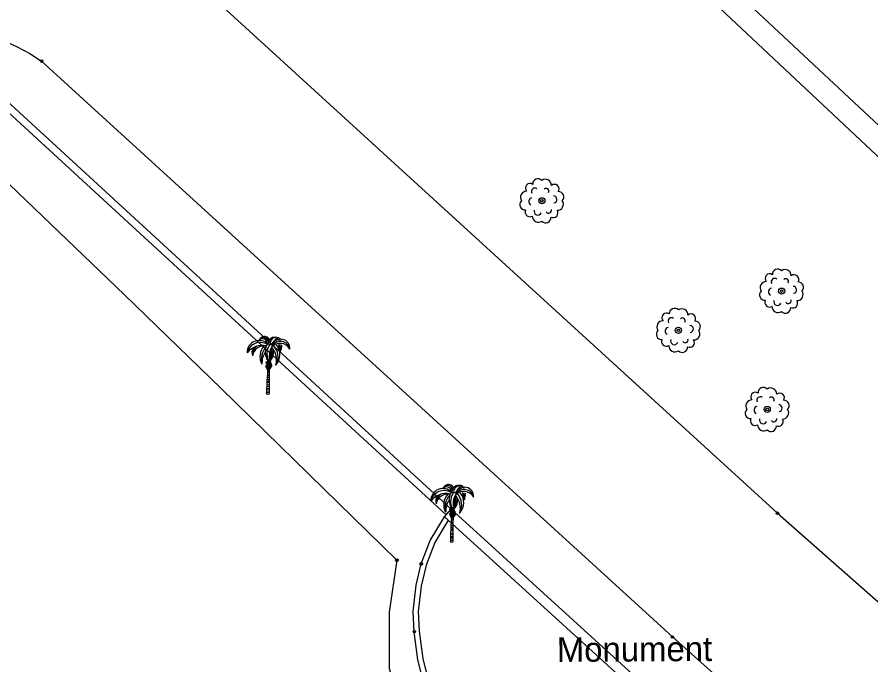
# Model space of a CAD drawing. Extents: x 344013 to 344423, y 298505 to 298795.
# Drawn here: x 344098.36 to 344132.25, y 298691.08 to 298716.8 of the extents above; entities that cross this region are included whole.
import ezdxf

# ---------------------------------------------------------------- set-up
doc = ezdxf.new("R2010")
doc.units = 0
for name, color, linetype in [('Default', 7, 'Continuous'), ('DH_CADRE -CARTOUCHE', 7, 'Continuous'), ('GO MUR EXTERIEUR', 7, 'Continuous'), ('PS_BOLT', 7, 'Continuous'), ('PS_CONST', 7, 'Continuous'), ('TOPO_POINT', 7, 'Continuous'), ('VOIRIE_BORDURE', 7, 'Continuous'), ('VOIRIE_ESPACE VERT', 7, 'Continuous')]:
    doc.layers.add(name, color=color, linetype=linetype)

# ---------------------------------------------------------------- blocks, each defined once
blk = doc.blocks.new('POINT_DISPLAY')
at = {"layer": 'Default'}
blk.add_circle((0, 0), 0.05, dxfattribs=at)
blk = doc.blocks.new('ARB1')
at = {"layer": 'Default'}
blk.add_circle((0, 0), 0.122, dxfattribs=at)
for centre, radius, start, end in [((-0.471, 0.503), 0.183, 53.9554, 222.2066), ((-0.153, 0.664), 0.211, 43.6925, 183.5969), ((0.139, 0.613), 0.241, 358.4583, 125.1928), ((-0.613, 0.139), 0.241, 88.4583, 215.1928), ((-0.276, 0.37), 0.134, 52.4396, 209.5496), ((0.164, 0.38), 0.112, 330.5895, 133.7127), ((0.501, 0.468), 0.183, 325.1444, 131.0175), ((0.664, 0.153), 0.211, 313.6925, 93.5969), ((-0.373, -0.024), 0.149, 103.7092, 242.3465), ((0.458, 0.052), 0.137, 276.6214, 88.967), ((0.613, -0.139), 0.241, 268.4583, 35.1928), ((-0.664, -0.153), 0.211, 133.6925, 273.5969), ((-0.478, -0.443), 0.19, 155.2243, 300.9377), ((-0.139, -0.613), 0.241, 178.4583, 305.1928), ((-0.163, -0.42), 0.148, 159.5371, 338.1663), ((0.153, -0.664), 0.211, 223.6925, 3.5969), ((0.271, -0.38), 0.112, 210.5895, 13.7127), ((0.448, -0.483), 0.188, 243.1323, 33.0297)]:
    blk.add_arc(centre, radius, start, end, dxfattribs=at)
blk = doc.blocks.new('PALMIER')
at = {"layer": 'Default'}
for p, q in [((0.066, 0.879), (-0.031, 0.865)), ((-0.027, 0.942), (0.068, 0.953)), ((0.07, 1.023), (-0.02, 1.046)), ((-0.016, 1.111), (0.072, 1.097)), ((-0.051, 0.409), (0.059, 0.425)), ((0.06, 0.53), (-0.047, 0.516)), ((-0.036, 0.77), (0.064, 0.807)), ((-0.062, 0.035), (0.058, 0.076)), ((0.058, 0.159), (-0.059, 0.156)), ((-0.057, 0.24), (0.058, 0.243)), ((0.058, 0.341), (-0.054, 0.323))]:
    blk.add_line(p, q, dxfattribs=at)
blk.add_lwpolyline([(-0.044, 0.591), (0.061, 0.593), (0.062, 0.664), (-0.041, 0.672)], dxfattribs=at)
for centre, radius, start, end in [((-0.427, 2.014), 0.606, 43.7538, 181.6042), ((-0.119, 2.5), 0.329, 122.4892, 158.9053), ((-0.196, 2.528), 0.242, 4.6636, 154.2427), ((-0.249, 2.465), 0.236, 4.3858, 134.352), ((-0.156, 2.558), 0.26, 21.2278, 122.4892), ((0.39, 2.418), 0.379, 113.9098, 175.4727), ((0.39, 2.418), 0.379, 113.9098, 175.4727), ((0.433, 2.437), 0.332, 97.2666, 184.0929), ((1.052, 1.956), 0.976, 126.8275, 153.3081), ((0.636, 2.223), 0.459, 356.3044, 159.1426), ((0.629, 2.092), 0.477, 12.2494, 148.4563), ((0.357, 2.315), 0.459, 69.2234, 105.0038), ((-1.014, 1.466), 1.819, 37.7085, 40.6574), ((-0.251, 2.185), 0.885, 28.6142, 37.2383), ((0.508, 2.682), 0.0691, 35.4622, 126.8275), ((-0.048, 2.285), 0.752, 25.9612, 35.4622), ((-0.287, 1.433), 0.935, 76.8807, 142.9442), ((-0.379, 1.861), 0.66, 58.0609, 166.7618), ((-0.298, 2.021), 0.491, 151.2749, 199.7359), ((-0.191, 1.77), 0.575, 78.6557, 171.4922), ((-0.318, 1.955), 0.441, 119.2251, 188.9038), ((0.377, 1.821), 0.768, 136.853, 208.9638), ((0.57, 1.687), 0.895, 137.8747, 194.5133), ((0.64, 2.063), 0.767, 153.2285, 230.2541), ((0.679, 1.97), 0.731, 142.4971, 222.4211), ((0, 2.373), 0.0573, 81.8892, 144.4453), ((-0.182, 1.095), 1.349, 71.5132, 81.8892), ((0.306, 2.506), 0.261, 198.8183, 199.9044), ((0.989, 1.84), 0.917, 144.1283, 203.5706), ((27.823, 0.039), 27.774, 175.6208, 176.7014), ((0.325, 2.055), 0.223, 141.9977, 191.6592), ((0.414, 2.001), 0.306, 136.5986, 162.2103), ((0.372, 1.986), 0.249, 133.2601, 172.8951), ((-0.403, 1.944), 0.63, 329.6083, 26.821), ((-0.287, 2.01), 0.575, 317.9696, 12.4803), ((0.609, 1.916), 0.559, 29.7072, 139.4934), ((-0.544, 1.637), 0.978, 345.0198, 41.2878), ((-0.338, 1.796), 0.844, 47.1184, 50.2648), ((-0.152, 1.926), 0.754, 51.3892, 54.6634), ((-0.338, 1.796), 0.844, 334.2104, 41.3357), ((-0.152, 1.926), 0.754, 315.2889, 39.1656), ((-1.727, 1.741), 2.37, 7.7396, 16.5083), ((-0.251, 2.185), 0.885, 351.03, 14.848), ((-0.484, 2.461), 1.182, 339.5014, 356.7342), ((0.671, 1.493), 0.966, 145.6563, 182.5945), ((-0.275, 1.529), 0.286, 2.2916, 36.7742), ((0.563, 1.714), 0.483, 137.337, 173.0404), ((0.322, 1.915), 0.23, 121.5714, 182.4317), ((0.388, 1.745), 0.282, 133.7373, 173.6287), ((0.832, 1.435), 0.791, 142.3775, 156.4217), ((0.255, 1.864), 0.149, 111.1145, 166.1173), ((0.42, 1.776), 0.361, 125.2003, 146.531), ((-0.764, 1.855), 0.939, 344.9923, 16.0405), ((-0.205, 1.197), 0.169, 353.506, 55.1211), ((-0.285, 1.344), 0.284, 348.9674, 47.5038), ((-0.721, 1.091), 0.712, 9.1555, 26.6687), ((-0.349, 1.239), 0.371, 353.6232, 41.3494), ((24.236, -0.46), 24.303, 175.1176, 178.9434), ((-0.586, 1.323), 0.604, 357.2226, 24.4977), ((0.287, 1.204), 0.266, 120.4076, 191.5492), ((-0.26, 1.395), 0.322, 340.1414, 25.8645), ((0.212, 1.553), 0.18, 167.086, 185.7383), ((0.343, 1.162), 0.295, 120.978, 179.2294), ((27.948, 0.208), 27.89, 177.2861, 180.4137), ((0.244, 1.306), 0.167, 110.7357, 185.3567), ((0.507, 1.019), 0.45, 131.0176, 160.1686)]:
    blk.add_arc(centre, radius, start, end, dxfattribs=at)

msp = doc.modelspace()

# ---------------------------------------------------------------- linework, layer by layer
at = {"layer": 'DH_CADRE -CARTOUCHE'}
for points in [[(344136.362, 298708.941), (344141.75, 298714.784), (344118.651, 298736.353), (344113.24, 298730.553)], [(344115.32, 298696.96), (344115.589, 298697.255), (344130.117, 298684.033), (344129.848, 298683.737)]]:
    msp.add_lwpolyline(points, close=True, dxfattribs=at)
msp.add_lwpolyline([(344114.63, 298689.833), (344114.27, 298691.284), (344114.125, 298692.395), (344114.078, 298693.197), (344114.201, 298694.239), (344114.4, 298695.091), (344114.756, 298696.022), (344115.32, 298696.96), (344115.471, 298696.822), (344114.936, 298695.934), (344114.591, 298695.033), (344114.398, 298694.204), (344114.279, 298693.191), (344114.324, 298692.414), (344114.467, 298691.322), (344114.82, 298689.897)], dxfattribs=at)
at = {"layer": 'GO MUR EXTERIEUR'}
msp.add_lwpolyline([(344118.651, 298736.353), (344141.75, 298714.784), (344136.362, 298708.941), (344113.24, 298730.553)], close=True, dxfattribs=at)
at = {"layer": 'PS_BOLT'}
msp.add_lwpolyline([(344136.362, 298708.941), (344135.692, 298708.293), (344122.611, 298720.578), (344112.611, 298729.909), (344113.24, 298730.553)], dxfattribs=at)
at = {"layer": 'VOIRIE_BORDURE'}
for points in [[(344135.251, 298763.339), (344119.175, 298746.216), (344104.333, 298729.921), (344103.629, 298728.425), (344103.178, 298726.908), (344102.994, 298725.349), (344103.009, 298724.152), (344103.293, 298722.366), (344103.622, 298721.156), (344104.336, 298719.642), (344105.154, 298718.475), (344128.542, 298697.099), (344156.76, 298672.229)], [(344066.641, 298688.625), (344090.832, 298714.382), (344091.46, 298714.944), (344092.393, 298715.535), (344093.275, 298715.95), (344094.045, 298716.161), (344094.983, 298716.297), (344095.976, 298716.287), (344096.908, 298716.148), (344097.634, 298715.942), (344098.359, 298715.623), (344098.865, 298715.357), (344099.332, 298715.052), (344124.372, 298692.186), (344148.812, 298670.333)]]:
    msp.add_lwpolyline(points, dxfattribs=at)
at = {"layer": 'VOIRIE_ESPACE VERT'}
msp.add_lwpolyline([(344115.386, 298697.034), (344095.685, 298715.142), (344067.379, 298684.161), (344067.261, 298683.991), (344067.218, 298683.388), (344067.403, 298682.745), (344071.702, 298678.318), (344092.045, 298659.877), (344116.981, 298686.713), (344117.24, 298686.552), (344092.063, 298659.455), (344071.494, 298678.102), (344067.135, 298682.59), (344066.915, 298683.356), (344066.967, 298684.094), (344067.145, 298684.349), (344095.667, 298715.566), (344115.589, 298697.255)], close=True, dxfattribs=at)
msp.add_lwpolyline([(344091.233, 298661.951), (344078.543, 298673.539), (344067.651, 298683.727), (344070.267, 298686.633), (344094.013, 298711.291), (344094.723, 298711.636), (344095.462, 298711.65), (344096.516, 298711.35), (344098.055, 298710.152), (344102.625, 298705.772), (344106.459, 298702.051), (344111.683, 298696.937), (344113.434, 298695.237), (344113.122, 298693.176), (344113.133, 298690.945), (344113.53, 298689.467), (344114.335, 298687.988), (344114.712, 298687.466), (344091.233, 298661.951)], dxfattribs=at)

# ---------------------------------------------------------------- block references
at = {"layer": 'TOPO_POINT'}
for p in [(344099.332, 298715.052), (344119.189, 298709.506), (344128.705, 298705.919), (344124.608, 298704.359), (344108.311, 298701.865), (344128.133, 298701.219), (344115.589, 298697.255), (344128.542, 298697.099), (344115.606, 298695.984), (344113.434, 298695.237), (344114.4, 298695.091), (344114.125, 298692.395), (344124.372, 298692.186)]:
    msp.add_blockref('POINT_DISPLAY', p, dxfattribs=at)
at = {"layer": 'VOIRIE_ESPACE VERT'}
for p in [(344119.189, 298709.506), (344128.705, 298705.919), (344124.608, 298704.359), (344128.133, 298701.219)]:
    msp.add_blockref('ARB1', p, dxfattribs=at)
at = {"layer": 'VOIRIE_ESPACE VERT', "xscale": 0.8, "yscale": 0.8000000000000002}
for p in [(344108.311, 298701.865), (344115.606, 298695.984)]:
    msp.add_blockref('PALMIER', p, dxfattribs=at)

# ---------------------------------------------------------------- texts
at = {"layer": 'PS_CONST'}
msp.add_text('Monument', height=0.9758, rotation=0.3665, dxfattribs=at).set_placement((344119.786, 298691.193))

doc.saveas('drawing.dxf')
